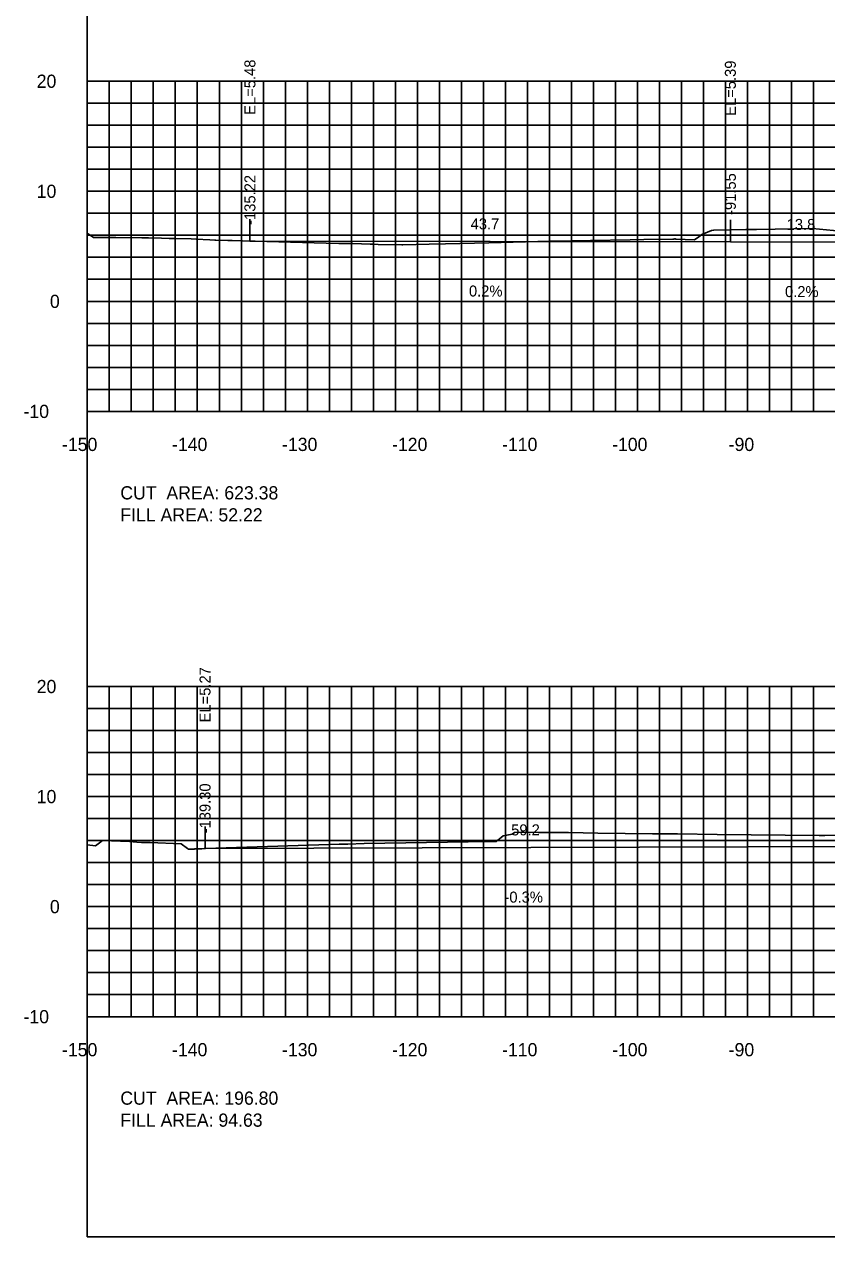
# Model space of a CAD drawing. Extents: x 1797419 to 1809236, y 248759 to 251512.
# Drawn here: x 1807575.3 to 1807648.2, y 250079.4 to 250189.6 of the extents above; entities that cross this region are included whole.
import ezdxf

# ---------------------------------------------------------------- set-up
doc = ezdxf.new("R2010")
doc.units = 0
for name, color, linetype in [('10', 7, 'Continuous'), ('3', 7, 'Continuous'), ('31', 7, 'Continuous'), ('4', 7, 'Continuous'), ('60', 7, 'Continuous'), ('ANNO-TXT', 7, 'Continuous'), ('CL-CNST', 7, 'Continuous'), ('Level 62', 7, 'Continuous'), ('M-ROADS', 7, 'Continuous')]:
    doc.layers.add(name, color=color, linetype=linetype)

msp = doc.modelspace()

# ---------------------------------------------------------------- linework, layer by layer
for p, q in [((1807595.78, 250169.91), (1807595.78, 250171.91)), ((1807639.45, 250169.83), (1807639.45, 250171.83)), ((1807591.7, 250114.71), (1807591.7, 250116.71))]:
    msp.add_line(p, q)
msp.add_lwpolyline([(1807581, 250079.43), (1807881, 250079.43), (1807881, 250269.43), (1807581, 250269.43)], close=True)
at = {"layer": '60'}
for p, q in [((1807580.94, 250184.43), (1807581, 250184.43)), ((1807581, 250154.43), (1807581, 250184.43)), ((1807580.94, 250174.43), (1807581, 250174.43)), ((1807580.94, 250164.43), (1807581, 250164.43)), ((1807580.94, 250154.43), (1807581, 250154.43)), ((1807581, 250154.43), (1807881, 250154.43)), ((1807581, 250154.37), (1807581, 250154.43)), ((1807591, 250154.37), (1807591, 250154.43)), ((1807601, 250154.37), (1807601, 250154.43)), ((1807611, 250154.37), (1807611, 250154.43)), ((1807621, 250154.37), (1807621, 250154.43)), ((1807631, 250154.37), (1807631, 250154.43)), ((1807641, 250154.37), (1807641, 250154.43)), ((1807580.94, 250129.43), (1807581, 250129.43)), ((1807581, 250099.43), (1807581, 250129.43)), ((1807580.94, 250119.43), (1807581, 250119.43)), ((1807580.94, 250109.43), (1807581, 250109.43)), ((1807580.94, 250099.43), (1807581, 250099.43)), ((1807581, 250099.43), (1807881, 250099.43)), ((1807581, 250099.37), (1807581, 250099.43)), ((1807591, 250099.37), (1807591, 250099.43)), ((1807601, 250099.37), (1807601, 250099.43)), ((1807611, 250099.37), (1807611, 250099.43)), ((1807621, 250099.37), (1807621, 250099.43)), ((1807631, 250099.37), (1807631, 250099.43)), ((1807641, 250099.37), (1807641, 250099.43))]:
    msp.add_line(p, q, dxfattribs=at)
at = {"layer": 'CL-CNST'}
for points in [[(1807595.78, 250169.91), (1807639.45, 250169.83), (1807653.24, 250169.8), (1807654.24, 250169.76), (1807654.32, 250169.76), (1807661.24, 250169.65), (1807662.34, 250169.61), (1807663.24, 250169.57), (1807663.51, 250169.57), (1807663.57, 250169.57), (1807663.74, 250169.07), (1807664.69, 250169.15), (1807665.74, 250169.23), (1807713.75, 250170.49), (1807715.75, 250170.54), (1807715.85, 250170.84), (1807715.92, 250171.04), (1807716.06, 250171.04), (1807716.25, 250171.04), (1807731, 250171.63)], [(1807591.7, 250114.71), (1807650.91, 250114.9), (1807651.91, 250114.86), (1807658.91, 250114.75), (1807660.91, 250114.67), (1807661.24, 250114.67), (1807661.41, 250114.17), (1807663.41, 250114.33), (1807711.43, 250115.59), (1807713.43, 250115.64), (1807713.6, 250116.14), (1807713.93, 250116.14), (1807722.91, 250116.5)]]:
    msp.add_lwpolyline(points, dxfattribs=at)
at = {"layer": 'Level 62'}
for p, q in [((1807581, 250184.43), (1807881, 250184.43)), ((1807581, 250154.43), (1807581, 250184.43)), ((1807583, 250154.43), (1807583, 250184.43)), ((1807585, 250154.43), (1807585, 250184.43)), ((1807587, 250154.43), (1807587, 250184.43)), ((1807589, 250154.43), (1807589, 250184.43)), ((1807591, 250154.43), (1807591, 250184.43)), ((1807593, 250154.43), (1807593, 250184.43)), ((1807595, 250154.43), (1807595, 250184.43)), ((1807597, 250154.43), (1807597, 250184.43)), ((1807599, 250154.43), (1807599, 250184.43)), ((1807601, 250154.43), (1807601, 250184.43)), ((1807603, 250154.43), (1807603, 250184.43)), ((1807605, 250154.43), (1807605, 250184.43)), ((1807607, 250154.43), (1807607, 250184.43)), ((1807609, 250154.43), (1807609, 250184.43)), ((1807611, 250154.43), (1807611, 250184.43)), ((1807613, 250154.43), (1807613, 250184.43)), ((1807615, 250154.43), (1807615, 250184.43)), ((1807617, 250154.43), (1807617, 250184.43)), ((1807619, 250154.43), (1807619, 250184.43)), ((1807621, 250154.43), (1807621, 250184.43)), ((1807623, 250154.43), (1807623, 250184.43)), ((1807625, 250154.43), (1807625, 250184.43)), ((1807627, 250154.43), (1807627, 250184.43)), ((1807629, 250154.43), (1807629, 250184.43)), ((1807631, 250154.43), (1807631, 250184.43)), ((1807633, 250154.43), (1807633, 250184.43)), ((1807635, 250154.43), (1807635, 250184.43)), ((1807637, 250154.43), (1807637, 250184.43)), ((1807639, 250154.43), (1807639, 250184.43)), ((1807641, 250154.43), (1807641, 250184.43)), ((1807643, 250154.43), (1807643, 250184.43)), ((1807645, 250154.43), (1807645, 250184.43)), ((1807647, 250154.43), (1807647, 250184.43)), ((1807581, 250182.43), (1807881, 250182.43)), ((1807581, 250180.43), (1807881, 250180.43)), ((1807581, 250178.43), (1807881, 250178.43)), ((1807581, 250176.43), (1807881, 250176.43)), ((1807581, 250174.43), (1807881, 250174.43)), ((1807581, 250172.43), (1807881, 250172.43)), ((1807581, 250170.43), (1807881, 250170.43)), ((1807581, 250168.43), (1807881, 250168.43)), ((1807581, 250166.43), (1807881, 250166.43)), ((1807581, 250164.43), (1807881, 250164.43)), ((1807581, 250162.43), (1807881, 250162.43)), ((1807581, 250160.43), (1807881, 250160.43)), ((1807581, 250158.43), (1807881, 250158.43)), ((1807581, 250156.43), (1807881, 250156.43)), ((1807581, 250154.43), (1807881, 250154.43)), ((1807581, 250129.43), (1807881, 250129.43)), ((1807581, 250099.43), (1807581, 250129.43)), ((1807583, 250099.43), (1807583, 250129.43)), ((1807585, 250099.43), (1807585, 250129.43)), ((1807587, 250099.43), (1807587, 250129.43)), ((1807589, 250099.43), (1807589, 250129.43)), ((1807591, 250099.43), (1807591, 250129.43)), ((1807593, 250099.43), (1807593, 250129.43)), ((1807595, 250099.43), (1807595, 250129.43)), ((1807597, 250099.43), (1807597, 250129.43)), ((1807599, 250099.43), (1807599, 250129.43)), ((1807601, 250099.43), (1807601, 250129.43)), ((1807603, 250099.43), (1807603, 250129.43)), ((1807605, 250099.43), (1807605, 250129.43)), ((1807607, 250099.43), (1807607, 250129.43)), ((1807609, 250099.43), (1807609, 250129.43)), ((1807611, 250099.43), (1807611, 250129.43)), ((1807613, 250099.43), (1807613, 250129.43)), ((1807615, 250099.43), (1807615, 250129.43)), ((1807617, 250099.43), (1807617, 250129.43)), ((1807619, 250099.43), (1807619, 250129.43)), ((1807621, 250099.43), (1807621, 250129.43)), ((1807623, 250099.43), (1807623, 250129.43)), ((1807625, 250099.43), (1807625, 250129.43)), ((1807627, 250099.43), (1807627, 250129.43)), ((1807629, 250099.43), (1807629, 250129.43)), ((1807631, 250099.43), (1807631, 250129.43)), ((1807633, 250099.43), (1807633, 250129.43)), ((1807635, 250099.43), (1807635, 250129.43)), ((1807637, 250099.43), (1807637, 250129.43)), ((1807639, 250099.43), (1807639, 250129.43)), ((1807641, 250099.43), (1807641, 250129.43)), ((1807643, 250099.43), (1807643, 250129.43)), ((1807645, 250099.43), (1807645, 250129.43)), ((1807647, 250099.43), (1807647, 250129.43)), ((1807581, 250127.43), (1807881, 250127.43)), ((1807581, 250125.43), (1807881, 250125.43)), ((1807581, 250123.43), (1807881, 250123.43)), ((1807581, 250121.43), (1807881, 250121.43)), ((1807581, 250119.43), (1807881, 250119.43)), ((1807581, 250117.43), (1807881, 250117.43)), ((1807581, 250115.43), (1807881, 250115.43)), ((1807581, 250113.43), (1807881, 250113.43)), ((1807581, 250111.43), (1807881, 250111.43)), ((1807581, 250109.43), (1807881, 250109.43)), ((1807581, 250107.43), (1807881, 250107.43)), ((1807581, 250105.43), (1807881, 250105.43)), ((1807581, 250103.43), (1807881, 250103.43)), ((1807581, 250101.43), (1807881, 250101.43)), ((1807581, 250099.43), (1807881, 250099.43))]:
    msp.add_line(p, q, dxfattribs=at)
at = {"layer": 'M-ROADS'}
for points in [[(1807581, 250170.57), (1807581.08, 250170.57), (1807581.56, 250170.23), (1807582.09, 250170.22), (1807582.26, 250170.22), (1807583.23, 250170.22), (1807583.59, 250170.22), (1807585.95, 250170.21), (1807586.29, 250170.21), (1807586.55, 250170.2), (1807587.74, 250170.17), (1807588.45, 250170.15), (1807588.96, 250170.13), (1807590.43, 250170.1), (1807590.9, 250170.09), (1807592.14, 250170.01), (1807592.58, 250169.98), (1807592.69, 250169.98), (1807593.76, 250169.97), (1807594.17, 250169.96), (1807595.1, 250169.93), (1807595.9, 250169.91), (1807596.25, 250169.9), (1807601.62, 250169.75), (1807602.7, 250169.73), (1807603.85, 250169.7), (1807604.3, 250169.69), (1807605.12, 250169.68), (1807606.7, 250169.64), (1807606.97, 250169.62), (1807607.45, 250169.6), (1807609.6, 250169.56), (1807609.67, 250169.56), (1807612.07, 250169.62), (1807613.56, 250169.66), (1807617.51, 250169.76), (1807621.94, 250169.88), (1807623, 250169.9), (1807623.13, 250169.9), (1807630.35, 250170.03), (1807631.59, 250170.05), (1807634.22, 250170.09), (1807634.32, 250170.09), (1807634.41, 250170.1), (1807634.44, 250170.1), (1807634.49, 250170.09), (1807636.18, 250170.02), (1807636.57, 250170.3), (1807636.85, 250170.51), (1807636.87, 250170.49), (1807637.74, 250170.86), (1807637.93, 250170.9), (1807637.94, 250170.9), (1807640.87, 250170.96), (1807641.22, 250170.96), (1807641.44, 250170.96), (1807641.82, 250170.97), (1807646.93, 250171.06), (1807652.64, 250170.51)], [(1807581, 250115.03), (1807581.73, 250114.96), (1807582.22, 250115.31), (1807582.25, 250115.34), (1807582.34, 250115.42), (1807582.35, 250115.43), (1807582.35, 250115.43), (1807582.38, 250115.43), (1807582.39, 250115.43), (1807584.84, 250115.36), (1807585.49, 250115.3), (1807585.93, 250115.27), (1807586.21, 250115.26), (1807586.7, 250115.26), (1807589.52, 250115.13), (1807590.12, 250114.71), (1807590.2, 250114.65), (1807590.53, 250114.66), (1807590.55, 250114.66), (1807590.57, 250114.66), (1807590.59, 250114.66), (1807590.62, 250114.66), (1807590.65, 250114.66), (1807590.68, 250114.66), (1807590.72, 250114.66), (1807590.76, 250114.67), (1807590.8, 250114.67), (1807590.86, 250114.67), (1807590.93, 250114.67), (1807591.01, 250114.68), (1807591.11, 250114.68), (1807591.23, 250114.69), (1807591.4, 250114.69), (1807591.62, 250114.7), (1807591.74, 250114.71), (1807597.39, 250114.88), (1807603.9, 250115.09), (1807603.9, 250115.09), (1807604.62, 250115.11), (1807604.69, 250115.11), (1807606.15, 250115.16), (1807615.61, 250115.33), (1807616.06, 250115.34), (1807616.19, 250115.34), (1807616.33, 250115.34), (1807616.45, 250115.34), (1807616.56, 250115.34), (1807616.65, 250115.34), (1807616.73, 250115.34), (1807616.81, 250115.34), (1807618.16, 250115.35), (1807618.61, 250115.71), (1807618.79, 250115.85), (1807619.62, 250116.02), (1807619.82, 250116.17), (1807620.45, 250116.2), (1807620.53, 250116.2), (1807620.57, 250116.2), (1807621.98, 250116.18), (1807622.25, 250116.18), (1807622.67, 250116.18), (1807623.05, 250116.17), (1807623.64, 250116.17), (1807624.73, 250116.15), (1807627.4, 250116.11), (1807632.36, 250116.05), (1807634.64, 250116.03), (1807638.24, 250115.99), (1807647.53, 250115.9), (1807647.86, 250115.9), (1807648.03, 250115.9), (1807653.54, 250115.95)]]:
    msp.add_lwpolyline(points, dxfattribs=at)

# ---------------------------------------------------------------- texts
at = {"layer": '10'}
for s, p in [('-150', (1807578.7, 250150.83)), ('-140', (1807588.7, 250150.83)), ('-130', (1807598.7, 250150.83)), ('-120', (1807608.7, 250150.83)), ('-110', (1807618.7, 250150.83)), ('-100', (1807628.7, 250150.83)), ('-90', (1807639.3, 250150.83)), ('-150', (1807578.7, 250095.83)), ('-140', (1807588.7, 250095.83)), ('-130', (1807598.7, 250095.83)), ('-120', (1807608.7, 250095.83)), ('-110', (1807618.7, 250095.83)), ('-100', (1807628.7, 250095.83)), ('-90', (1807639.3, 250095.83))]:
    msp.add_text(s, height=1.2, dxfattribs=at).set_placement(p)
at = {"layer": '3'}
for s, p in [('EL=5.48', (1807596.28, 250181.38)), ('EL=5.39', (1807639.95, 250181.29)), ('-135.22', (1807596.28, 250171.38)), ('-91.55', (1807639.95, 250172.28)), ('EL=5.27', (1807592.2, 250126.17)), ('-139.30', (1807592.2, 250116.09))]:
    msp.add_text(s, height=1, rotation=90, dxfattribs=at).set_placement(p)
at = {"layer": '31'}
for s, p in [('20', (1807576.4, 250183.83)), ('10', (1807576.4, 250173.83)), ('0', (1807577.6, 250163.83)), ('-10', (1807575.2, 250153.83)), ('20', (1807576.4, 250128.83)), ('10', (1807576.4, 250118.83)), ('0', (1807577.6, 250108.83)), ('-10', (1807575.2, 250098.83))]:
    msp.add_text(s, height=1.2, dxfattribs=at).set_placement(p)
at = {"layer": '4'}
for s, rotation, p in [('43.7', 359.8873, (1807615.84, 250170.97)), ('13.8', 359.8873, (1807644.57, 250170.92)), ('0.2%', 359.8873, (1807615.69, 250164.87)), ('0.2%', 359.8873, (1807644.42, 250164.82)), ('59.2', 0.1839, (1807619.53, 250115.9)), ('-0.3%', 0.1839, (1807618.92, 250109.79))]:
    msp.add_text(s, height=1, rotation=rotation, dxfattribs=at).set_placement(p)
at = {"layer": '60'}
for p in [(1807581, 250154.43), (1807581, 250099.43)]:
    msp.add_text('-', height=0.0001, dxfattribs=at).set_placement(p)
at = {"layer": 'ANNO-TXT'}
for s, p in [('CUT  AREA: 623.38', (1807584, 250146.43)), ('FILL AREA: 52.22', (1807584, 250144.43)), ('CUT  AREA: 196.80', (1807584, 250091.43)), ('FILL AREA: 94.63', (1807584, 250089.43))]:
    msp.add_text(s, height=1.2, dxfattribs=at).set_placement(p)

doc.saveas('drawing.dxf')
